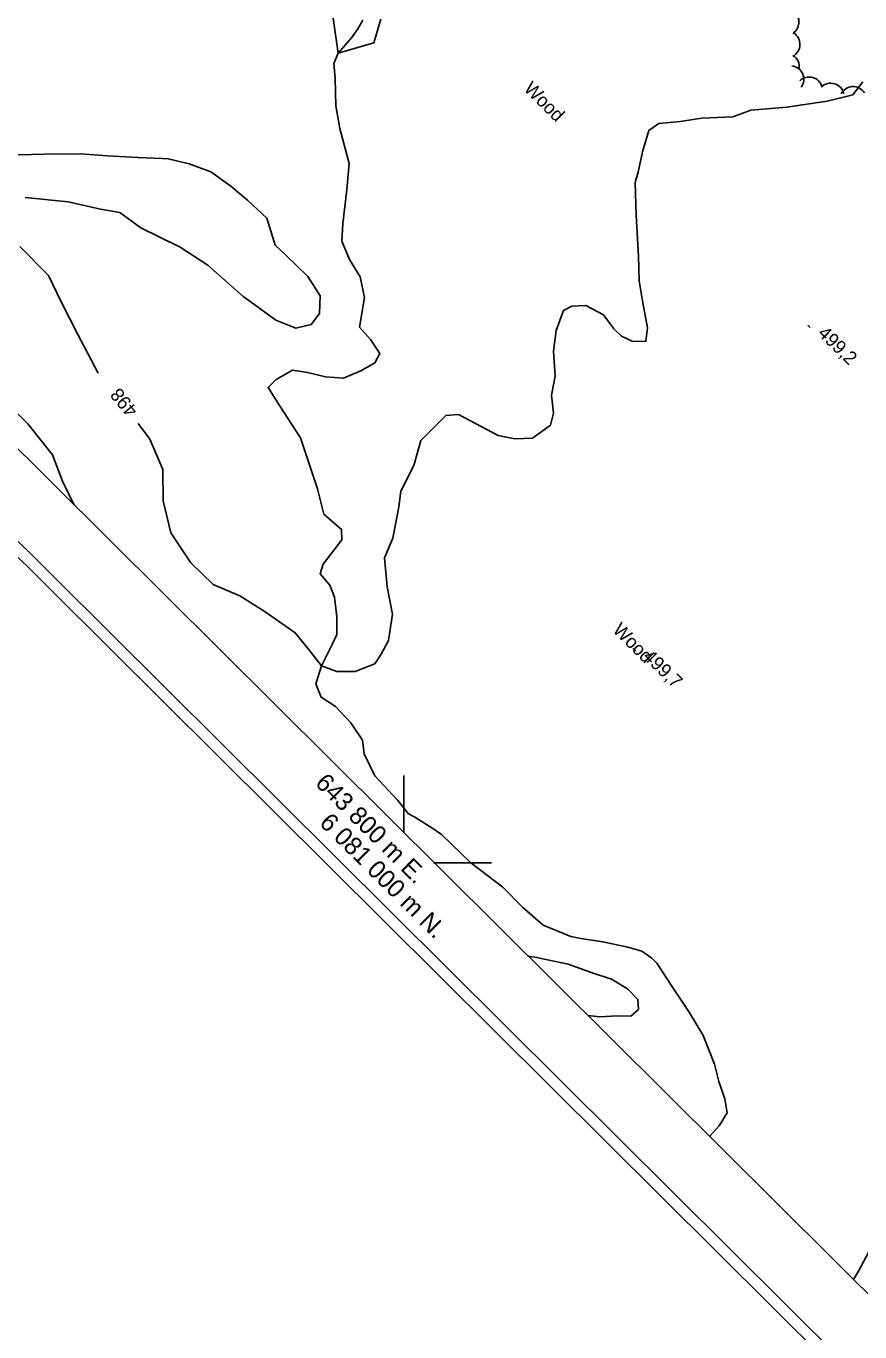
# Model space of a CAD drawing. Extents: x 642515 to 647219, y 6080136 to 6084356.
# Drawn here: x 643716 to 643901.4, y 6080895.6 to 6081186.1 of the extents above; entities that cross this region are included whole.
import ezdxf

# ---------------------------------------------------------------- set-up
doc = ezdxf.new("R2010")
doc.units = 0
for name, color, linetype in [('Level 1', 7, 'Continuous'), ('Level 2', 7, 'Continuous'), ('Level 3', 7, 'Continuous'), ('Level 4', 7, 'Continuous'), ('Level 44', 7, 'Continuous'), ('Level 60', 7, 'Continuous'), ('Level 61', 7, 'Continuous')]:
    doc.layers.add(name, color=color, linetype=linetype)

msp = doc.modelspace()

# ---------------------------------------------------------------- linework, layer by layer
at = {"layer": 'Level 1'}
for points in [[(643688.91, 6081117.05), (643690.75, 6081119.16), (643693.86, 6081119.29), (643700.14, 6081117.7), (643703.79, 6081115.7), (643706.35, 6081113.46), (643708.85, 6081108.42), (643712.87, 6081101.15), (643716.39, 6081097.62), (643721.82, 6081090.76), (643724.06, 6081084.9), (643726.64, 6081079.54)], [(643827.58, 6080979.22), (643829.51, 6080978.92), (643836.5, 6080977.46), (643842.08, 6080975.43), (643846.18, 6080974.1), (643849.69, 6080971.92), (643852.01, 6080969.59), (643852.16, 6080967.36), (643850.42, 6080965.88), (643847.45, 6080965.92), (643843.54, 6080965.74), (643840.88, 6080966)]]:
    msp.add_lwpolyline(points, dxfattribs=at)
at = {"layer": 'Level 2'}
for points in [[(643794.88, 6081187.64), (643793.31, 6081182.4), (643785.36, 6081180.14), (643784.15, 6081188.42)], [(643740.91, 6081097.68), (643743.48, 6081094.22), (643746.35, 6081087.5), (643746.42, 6081080.52), (643748.19, 6081073.41), (643752.57, 6081066.71), (643757.55, 6081061.9), (643763.49, 6081059.41), (643769.11, 6081055.85), (643775.84, 6081051.15), (643779.08, 6081047.11), (643781.68, 6081043.81), (643785.06, 6081042.51), (643789.15, 6081042.54), (643793.52, 6081044.28), (643794.9, 6081046.38), (643796.54, 6081049.46), (643797.42, 6081055.3), (643796.28, 6081061.41), (643795.69, 6081067.8), (643797.55, 6081072.18), (643798.84, 6081079.17), (643799.33, 6081082.66), (643802.22, 6081088.39), (643803.77, 6081093.95), (643807.45, 6081097.65), (643809.33, 6081099.46), (643812.12, 6081099.73), (643815.94, 6081097.74), (643820.94, 6081095.02), (643824.67, 6081094.3), (643828.59, 6081094.48), (643832.56, 6081097.32), (643833.26, 6081100.01), (643832.83, 6081104), (643833.66, 6081108.23), (643833.28, 6081113.83), (643833.85, 6081118.44), (643835.47, 6081122.88), (643837.33, 6081123.81), (643840.45, 6081123.94), (643844.36, 6081121.87), (643846.65, 6081118.81), (643848.37, 6081117.16), (643850.93, 6081115.97), (643853.82, 6081116), (643854.18, 6081118.99), (643853.15, 6081124.54), (643852.34, 6081129.47), (643852.13, 6081134.91), (643851.66, 6081144.03), (643851.41, 6081151.32), (643852.05, 6081153.61), (643853.02, 6081158.17), (643854.46, 6081162.92), (643856.68, 6081164.43), (643861.46, 6081164.91), (643866.14, 6081165.63), (643873.17, 6081165.93), (643877.16, 6081167.4), (643885.13, 6081168.09), (643894.1, 6081169.41), (643899.85, 6081170.84), (643902.06, 6081173.71)], [(643711.39, 6081157.41), (643720.03, 6081157.67), (643728.05, 6081157.72), (643734.09, 6081157.24), (643740.85, 6081156.89), (643746.24, 6081156.68), (643747.53, 6081156.61)], [(643747.53, 6081156.61), (643752.25, 6081155.48), (643757.02, 6081153.71), (643761.49, 6081150.55), (643765.23, 6081147.43), (643769.51, 6081143.38), (643771.36, 6081137.4), (643773.67, 6081135.23), (643778.65, 6081130.42), (643781.35, 6081126.1), (643781.22, 6081122.16), (643779.38, 6081119.71), (643775.99, 6081118.92), (643771.53, 6081120.71), (643764.19, 6081126.08), (643756.35, 6081132.95), (643750.22, 6081136.96), (643741.51, 6081141.27), (643736.79, 6081144.65), (643732.49, 6081145.41), (643725.33, 6081147.02), (643715.8, 6081147.99)], [(643714.59, 6081137.1), (643720.97, 6081130.62), (643723.86, 6081124.63), (643727.38, 6081117.64), (643732.03, 6081108.95)]]:
    msp.add_lwpolyline(points, dxfattribs=at)
at = {"layer": 'Level 3'}
for p, q in [((643889.79, 6081119.6), (643890.36, 6081119.04)), ((643850.95, 6081047.65), (643851.52, 6081047.09))]:
    msp.add_line(p, q, dxfattribs=at)
at = {"layer": 'Level 4'}
for points in [[(643790.8, 6081027.24), (643788.22, 6081031.16), (643784.77, 6081034.79), (643781.58, 6081036.82), (643780.42, 6081039.8), (643781.68, 6081043.81), (643784.02, 6081048.54), (643785.08, 6081050.78), (643785.06, 6081054.72), (643784.53, 6081059.1), (643783.55, 6081061.76), (643781.37, 6081064.27), (643782.03, 6081066.4), (643786.17, 6081071.82), (643786.1, 6081074.14), (643782.18, 6081077.58), (643780.76, 6081083.19), (643776.96, 6081094.5), (643772.31, 6081101.74), (643769.8, 6081105.75), (643771.61, 6081107.48), (643775.25, 6081109.57), (643778.57, 6081109.07), (643782.57, 6081108.13), (643786.52, 6081107.83), (643790.59, 6081109.54), (643793.53, 6081111.18), (643794.6, 6081113.26), (643792.54, 6081116.42), (643790.11, 6081119.15), (643791.2, 6081125.73), (643790.26, 6081130.32), (643787.91, 6081134.19), (643786.2, 6081138.25), (643786.43, 6081142.12), (643787.28, 6081149.81), (643787.79, 6081155.55), (643785.74, 6081163.37), (643784.85, 6081168.37), (643784.68, 6081174.55), (643784.39, 6081177.82), (643785.36, 6081180.14), (643788.35, 6081183.55), (643789.74, 6081185.49), (643790.82, 6081187.41)], [(643867.92, 6080939.12), (643870.12, 6080941.5), (643871.85, 6080944.34), (643871.32, 6080947.51), (643870.02, 6080951.34), (643869.05, 6080955.2), (643866.54, 6080961.6), (643863.39, 6080966.76), (643859.57, 6080972.51), (643856.26, 6080977.65), (643855.14, 6080978.78), (643852.88, 6080980.31), (643849.78, 6080981.22), (643844.25, 6080982.44), (643839.32, 6080983.15), (643837.13, 6080983.56), (643830.95, 6080986.1), (643826.36, 6080990.12), (643821.98, 6080994.55), (643814.89, 6081000), (643808.38, 6081006.28), (643806.21, 6081007.74), (643802.44, 6081010.13), (643801.03, 6081010.91), (643798.67, 6081013.88), (643793.49, 6081019.32), (643791.16, 6081024.22), (643790.8, 6081027.24)], [(643955.39, 6080896.1), (643950.86, 6080900.35), (643943.96, 6080905.33), (643939.2, 6080908.3), (643934.22, 6080912.04), (643929.86, 6080915.11), (643925.19, 6080919.04), (643921.68, 6080920), (643914.39, 6080921.27), (643910.26, 6080920.83), (643906.32, 6080917.36), (643903.45, 6080913.56), (643901.1, 6080909.15), (643899.94, 6080907.3)]]:
    msp.add_lwpolyline(points, dxfattribs=at)
at = {"layer": 'Level 44'}
for centre, start, end in [((643884.83, 6081187.02), 303.0303, 63.0082), ((643885.06, 6081182.05), 298.316, 58.294), ((643884.91, 6081177.05), 351.9717, 58.294), ((643885.92, 6081174.3), 323.4102, 83.3881), ((643890.09, 6081171.8), 13.815, 133.7929), ((643894.9, 6081170.42), 14.3127, 134.2906), ((643899.88, 6081169.67), 32.4396, 152.4176)]:
    msp.add_arc(centre, 3, start, end, dxfattribs=at)
at = {"layer": 'Level 60'}
for p, q in [((643800, 6081006.63), (643800, 6081019.4)), ((643806.59, 6081000), (643819.44, 6081000))]:
    msp.add_line(p, q, dxfattribs=at)
for points in [[(643756.15, 6083509.1), (645893.11, 6081385.05), (644652.25, 6080135.58), (642514.75, 6082260.08)], [(642518.29, 6082260.09), (643756.16, 6083505.56), (645889.57, 6081385.04), (644651.74, 6080139.63)], [(643756.23, 6083485.06), (645517.55, 6081734.46), (644300.6, 6080509.08), (642538.79, 6082260.16)]]:
    msp.add_lwpolyline(points, close=True, dxfattribs=at)

# ---------------------------------------------------------------- texts
at = {"layer": 'Level 2'}
msp.add_text('498', height=3, rotation=128.9817, dxfattribs=at).set_placement((643740.99, 6081100.7))
at = {"layer": 'Level 3'}
for s, p in [('499,2', (643891.82, 6081117.56)), ('499,7', (643852.98, 6081045.6))]:
    msp.add_text(s, height=3, rotation=315.59, dxfattribs=at).set_placement(p)
at = {"layer": 'Level 44'}
for p in [(643826.45, 6081171.98), (643846.22, 6081051.56)]:
    msp.add_text('Wood', height=3, rotation=315.1749, dxfattribs=at).set_placement(p)
at = {"layer": 'Level 61'}
for s, p in [('643 800 m E.', (643780.03, 6081017.46)), ('6 081 000 m N.', (643780.98, 6081008.62))]:
    msp.add_text(s, height=4, rotation=315.175, dxfattribs=at).set_placement(p)

doc.saveas('drawing.dxf')
